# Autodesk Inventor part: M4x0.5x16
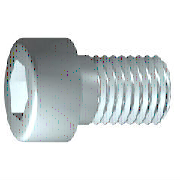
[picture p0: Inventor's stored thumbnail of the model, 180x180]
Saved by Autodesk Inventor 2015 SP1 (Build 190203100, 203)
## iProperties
Created: 2014-07
Part Number: M4x0.5x16
Material: 강, 연강
Description: 6각머리 태핑 나사
Document SubType Name: Modeling
Standard: KS B 1003
Designer: KYOUNG IL JANG
Standards Organization: KS
Language: ko-KR
Size Designation: M 4 x 16
Categories: <MemberInstance><Categories><Category DisplayName="조임쇠" InternalName="e4da775c-781d-43d5-af7c-5136215cf5a6" Mnemonic="FSTN"><Category DisplayName="볼트" InternalN
Density: 1 g/cm^3
Appearance: 강철
Company: 한국ATC센터
IsCustomPart: 1
Author: KYOUNG IL JANG
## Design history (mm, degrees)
sketch "스케치1"
  geometry: L1 (-1, 0)-(16, 0); L2 (16, 0)-(16, 2); L3 (16, 2)-(1.75, 2); L4 (1.75, 2)-(1.32, 2); L5 (1.32, 2)-(0, 2); L6 (0, 2)-(0, 3.5); L7 (0, 3.5)-(-4, 3.5); L8 (-4, 3.5)-(-4, 1.732); L9 (-4, 1.732)-(-2, 1.732); L10 (-2, 1.732)-(-1, 0); L11 (-8, 0)-(20, 0) reference; L12 (0, -0.7)-(0, 4.2) reference; L13 (1.75, 2)-(0, 2)
  constraints: 22 end point, 6 parallel, 2 collinear, 2 perpendicular, 1 horizontal, 1 point on line
  dimensions: "d1" = 14.25 distance from line of L3.end L2 (= GEL); "d2" = 0.42952 distance of L4.end L3.end (computed from GAL); "d3" = 4 distance between parallel lines of L8 L6 (= KOH); "d4" = 2 distance of L8.end L9.end (= INTI); "d5" = 60 deg angle of L10 L1; "d6" = 4 diameter of L3 L1 (= GD); "d7" = 4 diameter of L5 L1 (= BDM); "d8" = 3.4641 diameter of L9 L1 (= 1.1547 x SW); "d9" = 7 diameter of L7 L1 (= KOD); "d26" = 16 distance between parallel lines of L12 L2 (= NLG)
revolve "본체" sketch "스케치1" stored, may be unused: angle "d10" = 90 deg
sketch "스케치2"
  geometry: L1 (0, -4.9)-(0, 4.9) reference; L2 (-4.9, 0)-(4.9, 0) reference; L3 (1.732, 0)-(0.866, -1.5); L4 (0.866, -1.5)-(-0.866, -1.5); L5 (-0.866, -1.5)-(-1.732, 0); L6 (-1.732, 0)-(-0.866, 1.5); L7 (-0.866, 1.5)-(0.866, 1.5); L8 (0.866, 1.5)-(1.732, 0); 2 further points
  constraints: 12 end point, 1 coincident, 1 horizontal alignment, 1 point on line, 12 other
extrude "슬롯" join sketch "스케치2" stored distance "d11" = 10; taper "d12" = 0 deg
workplane "Work Plane1"
fillet "Fillet2" dims "d30" = 0.1 (= R)
body "Solid1"
fillet "모깎기1" dims "d17" = 0.4 (= RR)
feature "스레드" dims "d13" = 14.25 (= GEL), "d14" = 0
chamfer "모따기1" distance "d15" = 0.42941 (= -0.5 x SPD + 0.5 x GD); stored, may be unused: second distance "d16" = 0.42941 (= GUL), angle "d27" = 45 deg
other parameters: "GD" = 4 (= NND) [user parameter; used in 2 equation terms], "NLG" = 16 [user parameter; used in 1 equation term], "GEL" = 14.25 [user parameter; used in 2 equation terms], "KOD" = 7 [user parameter; used in 1 equation term], "KOH" = 4 [user parameter; used in 1 equation term], "INTI" = 2 [user parameter; used in 1 equation term], "GAL" = 0.42941 (= 0.61345 x PTC) [user parameter; used in 1 equation term], "GUL" = 0.42941 (= 0.61345 x PTC) [user parameter; used in 1 equation term], "BDM" = 4 (= NND) [user parameter; used in 1 equation term], "SW" = 3 [user parameter; used in 2 equation terms], "RR" = 0.4 [user parameter; used in 1 equation term], "SPD" = 3.14117 (= NND - 1.2269 x PTC) [user parameter; used in 1 equation term], "d19" = 0, "d28" = 0, "d29" = 0, "R" = 0.1 [user parameter; used in 1 equation term], "PHH" = 0.2 [user parameter], "GD1" = 3.14117 (= THREADDIA - 1.2269 x PTC) [user parameter], "THREADDIA" = 4 [user parameter; used in 1 equation term], "FAWI" = 45 deg [user parameter], "TPU" = 14.28571 (computed from PTC) [user parameter], "PTC" = 0.7 [user parameter; used in 5 equation terms], "NND" = 4 [user parameter; used in 3 equation terms], "TOA" = 30 deg [user parameter], "E0" = 3.465 (= 1.155 x SW) [user parameter]
